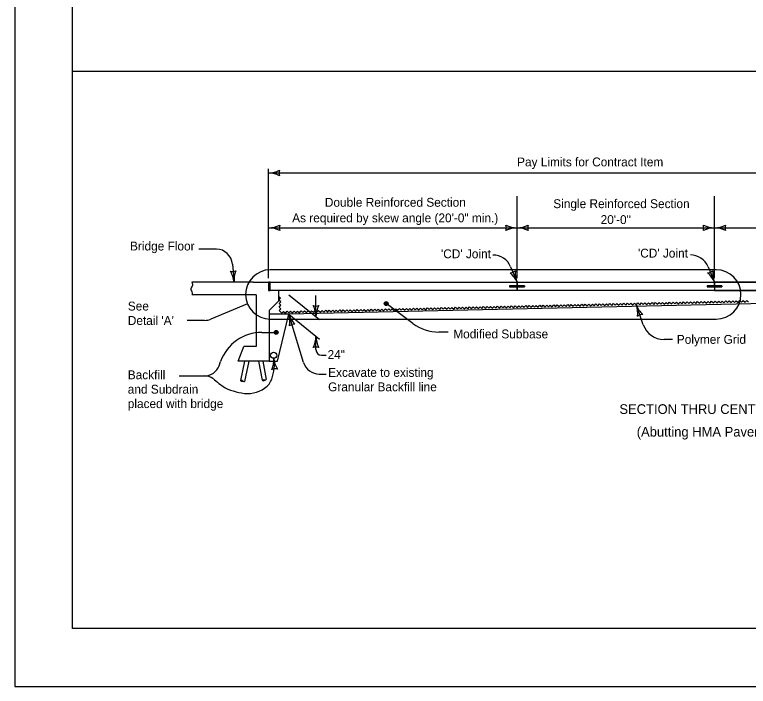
# Model space of a CAD drawing. Extents: x -2135039 to -2124495, y -2139046 to -2132546.
# Drawn here: x -2131439 to -2130115, y -2135130 to -2133919 of the extents above; entities that cross this region are included whole.
import ezdxf

# ---------------------------------------------------------------- set-up
doc = ezdxf.new("R2010")
doc.units = 0
for name, color, linetype in [('BridgeSuperStructureExisting', 7, 'Continuous'), ('dsnAlignmentCurveData', 7, 'Continuous'), ('dsnAlignmentStation', 7, 'Continuous'), ('dsnStdLabel', 7, 'Continuous'), ('dsnStdLineWork', 7, 'Continuous')]:
    doc.layers.add(name, color=color, linetype=linetype)

msp = doc.modelspace()

# ---------------------------------------------------------------- linework, layer by layer
at = {"layer": 'BridgeSuperStructureExisting'}
for p, q in [((-2130980.5, -2134393.9), (-2130980.5, -2134196.9)), ((-2130980.5, -2134204.3), (-2129819.2, -2134204.3)), ((-2130532, -2134393.9), (-2130532, -2134246.4)), ((-2130175.6, -2134393.9), (-2130175.6, -2134246.4)), ((-2130980.5, -2134303.3), (-2130532, -2134303.3)), ((-2130532, -2134303.3), (-2130175.6, -2134303.3)), ((-2130175.6, -2134303.3), (-2129819.2, -2134303.3)), ((-2131074.8, -2134341.7), (-2131106.5, -2134341.7)), ((-2131045.7, -2134368.9), (-2131042.9, -2134401.4)), ((-2130543.6, -2134373.6), (-2130532, -2134401.4)), ((-2130187.2, -2134373.6), (-2130175.6, -2134401.4)), ((-2130172.4, -2134379.1), (-2130977.5, -2134379.1)), ((-2131008.7, -2134401.4), (-2131119.3, -2134401.4)), ((-2131008.7, -2134401.4), (-2130980.5, -2134401.4)), ((-2130980.5, -2134401.4), (-2130980.5, -2134416.2)), ((-2130977.5, -2134401.4), (-2130980.5, -2134401.4)), ((-2130980.5, -2134404.7), (-2130977.5, -2134401.8)), ((-2130980.5, -2134402.6), (-2130979.6, -2134401.8)), ((-2130977.5, -2134401.8), (-2130980.5, -2134401.8)), ((-2130980.5, -2134406.8), (-2130977.5, -2134403.9)), ((-2130977.5, -2134401.4), (-2129819.2, -2134401.4)), ((-2130532, -2134416.2), (-2130532, -2134401.4)), ((-2129819.2, -2134401.4), (-2130175.6, -2134401.4)), ((-2130175.6, -2134401.4), (-2130175.6, -2134407.9)), ((-2130175.6, -2134401.4), (-2130175.6, -2134416.2)), ((-2130980.5, -2134408.9), (-2130977.5, -2134406)), ((-2130980.5, -2134411), (-2130977.5, -2134408.1)), ((-2130980.5, -2134413.1), (-2130977.5, -2134410.2)), ((-2130980.5, -2134415.2), (-2130977.5, -2134412.3)), ((-2130980.5, -2134416.2), (-2130977.5, -2134416.2)), ((-2130979.3, -2134416.2), (-2130977.5, -2134414.4)), ((-2129819.2, -2134416.2), (-2130977.5, -2134416.2)), ((-2130962.7, -2134416.2), (-2130962.7, -2134435.5)), ((-2130545.4, -2134407.9), (-2130518.7, -2134407.9)), ((-2130545.4, -2134409.7), (-2130518.7, -2134409.7)), ((-2130545.4, -2134409.7), (-2130518.7, -2134409.7)), ((-2130518.7, -2134407.9), (-2130518.7, -2134409.7)), ((-2130189, -2134407.9), (-2130162.3, -2134407.9)), ((-2130189, -2134409.7), (-2130162.3, -2134409.7)), ((-2130175.6, -2134407.9), (-2130162.3, -2134407.9)), ((-2130162.3, -2134409.7), (-2130175.6, -2134409.7)), ((-2130175.6, -2134409.7), (-2130175.6, -2134416.2)), ((-2130175.6, -2134416.2), (-2129819.2, -2134416.2)), ((-2130162.3, -2134407.9), (-2130162.3, -2134409.7)), ((-2130162.3, -2134407.9), (-2130162.3, -2134409.7)), ((-2131002.8, -2134424.3), (-2131119.3, -2134424.3)), ((-2131002.8, -2134424.3), (-2131002.8, -2134517.2)), ((-2130943.9, -2134424), (-2130888.6, -2134469)), ((-2130895.1, -2134463.7), (-2130895.1, -2134425.6)), ((-2131018.7, -2134440.7), (-2131084.9, -2134468)), ((-2130962.7, -2134435.5), (-2130979.5, -2134452.3)), ((-2129819.2, -2134433.9), (-2130943.9, -2134459.3)), ((-2130720.3, -2134475.7), (-2130768.3, -2134440.1)), ((-2130304.1, -2134478.3), (-2130316.6, -2134442.4)), ((-2130979.5, -2134452.3), (-2130979.5, -2134543.9)), ((-2131096.2, -2134470.3), (-2131127.8, -2134470.3)), ((-2130943.9, -2134459.3), (-2130979.5, -2134459.3)), ((-2130977.5, -2134468.2), (-2130172.4, -2134468.2)), ((-2130964.6, -2134543.9), (-2130943.9, -2134459.3)), ((-2130943.9, -2134459.3), (-2130888.6, -2134504.3)), ((-2130917.4, -2134546.2), (-2130943.9, -2134459.3)), ((-2130656.2, -2134491.3), (-2130673.1, -2134491.3)), ((-2130895.1, -2134523), (-2130895.1, -2134499)), ((-2130251.3, -2134504.9), (-2130266.7, -2134504.9)), ((-2131035.4, -2134543.9), (-2131025.2, -2134517.2)), ((-2131002.8, -2134517.2), (-2131025.2, -2134517.2)), ((-2130885.1, -2134533), (-2130876.5, -2134533)), ((-2130979.5, -2134543.9), (-2131035.4, -2134543.9)), ((-2131024, -2134543.9), (-2131031.5, -2134578.7)), ((-2131016.4, -2134543.9), (-2131024.2, -2134580.3)), ((-2130998.7, -2134543.9), (-2130992.4, -2134578.3)), ((-2130991.2, -2134543.9), (-2130985.1, -2134576.9)), ((-2130979.5, -2134543.9), (-2130964.6, -2134543.9)), ((-2130889, -2134567.2), (-2130876.5, -2134567.2))]:
    msp.add_line(p, q, dxfattribs=at)
for points in [[(-2130959.7, -2134454.3), (-2130961.5, -2134452.7), (-2130958.4, -2134449.4), (-2130961.6, -2134446.3), (-2130958.5, -2134443.1), (-2130961.7, -2134440), (-2130958.7, -2134436.8), (-2130961.9, -2134433.7), (-2130958.8, -2134430.4), (-2130962, -2134427.3), (-2130961.9, -2134427.2)], [(-2130768, -2134436.9), (-2130769.2, -2134437.5), (-2130771, -2134438), (-2130771.3, -2134439.9), (-2130771.1, -2134441.5), (-2130769.9, -2134443), (-2130768.2, -2134442.8), (-2130766.4, -2134442.6), (-2130765.5, -2134441.1), (-2130765.3, -2134439.6), (-2130766.4, -2134437.6), (-2130767.7, -2134437.4), (-2130769.5, -2134437.9), (-2130771, -2134439), (-2130771, -2134440.8), (-2130769.8, -2134442.2), (-2130768.2, -2134442.3), (-2130766.4, -2134442), (-2130766.1, -2134440.9), (-2130765.7, -2134439.7), (-2130766.6, -2134438.2), (-2130767.9, -2134438.2), (-2130769.4, -2134438.5), (-2130770.5, -2134439.3), (-2130770, -2134440.8), (-2130768.8, -2134441.7), (-2130767.3, -2134441.8), (-2130766.9, -2134441), (-2130766.4, -2134440), (-2130767.2, -2134438.8), (-2130768.3, -2134438.6), (-2130769.3, -2134439.1), (-2130769.4, -2134440.2), (-2130768.8, -2134441), (-2130767.8, -2134441.3), (-2130767.3, -2134440.9), (-2130767, -2134440.3), (-2130767.6, -2134439.3), (-2130768.3, -2134439.2), (-2130769, -2134439.6), (-2130768.9, -2134440.2), (-2130768.4, -2134440.6), (-2130767.6, -2134440.6), (-2130767.7, -2134440.1), (-2130768.3, -2134439.8)], [(-2130597.2, -2134447.2), (-2130595.6, -2134448.7), (-2130592.5, -2134445.5), (-2130589.2, -2134448.6), (-2130586.1, -2134445.3), (-2130582.9, -2134448.4), (-2130579.8, -2134445.2), (-2130576.6, -2134448.3), (-2130573.5, -2134445), (-2130570.2, -2134448.1), (-2130567.1, -2134444.9), (-2130563.9, -2134448), (-2130560.8, -2134444.7), (-2130557.6, -2134447.8), (-2130554.5, -2134444.6), (-2130551.2, -2134447.7), (-2130548.1, -2134444.4), (-2130544.9, -2134447.5), (-2130541.8, -2134444.3), (-2130538.6, -2134447.4), (-2130535.5, -2134444.1), (-2130532.2, -2134447.2), (-2130529.1, -2134444), (-2130525.9, -2134447.1), (-2130522.8, -2134443.8), (-2130521.2, -2134445.4)], [(-2130521.2, -2134445.4), (-2130519.6, -2134446.9), (-2130516.5, -2134443.7), (-2130513.2, -2134446.8), (-2130510.1, -2134443.5), (-2130506.9, -2134446.6), (-2130503.8, -2134443.4), (-2130500.6, -2134446.5), (-2130497.5, -2134443.2), (-2130494.2, -2134446.3), (-2130491.1, -2134443.1), (-2130487.9, -2134446.2), (-2130484.8, -2134442.9), (-2130481.6, -2134446), (-2130478.5, -2134442.8), (-2130475.2, -2134445.9), (-2130472.1, -2134442.6), (-2130468.9, -2134445.7), (-2130465.8, -2134442.5), (-2130462.6, -2134445.6), (-2130459.5, -2134442.3), (-2130456.2, -2134445.4), (-2130453.1, -2134442.2), (-2130449.9, -2134445.3), (-2130446.8, -2134442), (-2130445.2, -2134443.6)], [(-2130445.2, -2134443.6), (-2130443.6, -2134445.1), (-2130440.5, -2134441.9), (-2130437.2, -2134445), (-2130434.1, -2134441.7), (-2130430.9, -2134444.8), (-2130427.8, -2134441.6), (-2130424.6, -2134444.7), (-2130421.5, -2134441.4), (-2130418.2, -2134444.5), (-2130415.1, -2134441.3), (-2130411.9, -2134444.4), (-2130408.8, -2134441.1), (-2130405.5, -2134444.2), (-2130402.5, -2134441), (-2130399.2, -2134444.1), (-2130396.1, -2134440.8), (-2130392.9, -2134443.9), (-2130389.8, -2134440.7), (-2130386.5, -2134443.8), (-2130383.5, -2134440.5), (-2130380.2, -2134443.6), (-2130377.1, -2134440.4), (-2130373.9, -2134443.5), (-2130370.8, -2134440.2), (-2130369.2, -2134441.8)], [(-2130369.2, -2134441.8), (-2130367.5, -2134443.4), (-2130364.4, -2134440.1), (-2130361.2, -2134443.2), (-2130358.1, -2134440), (-2130354.9, -2134443.1), (-2130351.8, -2134439.8), (-2130348.5, -2134442.9), (-2130345.4, -2134439.7), (-2130342.2, -2134442.8), (-2130339.1, -2134439.5), (-2130335.9, -2134442.6), (-2130332.8, -2134439.4), (-2130329.5, -2134442.5), (-2130326.4, -2134439.2), (-2130323.2, -2134442.3), (-2130320.1, -2134439.1), (-2130316.9, -2134442.2), (-2130313.8, -2134438.9), (-2130310.5, -2134442), (-2130307.4, -2134438.8), (-2130304.2, -2134441.9), (-2130301.1, -2134438.6), (-2130297.9, -2134441.7), (-2130294.8, -2134438.5), (-2130293.2, -2134440)], [(-2130293.2, -2134440), (-2130291.5, -2134441.6), (-2130288.4, -2134438.3), (-2130285.2, -2134441.4), (-2130282.1, -2134438.2), (-2130278.9, -2134441.3), (-2130275.8, -2134438), (-2130272.5, -2134441.1), (-2130269.4, -2134437.9), (-2130266.2, -2134441), (-2130263.1, -2134437.8), (-2130259.9, -2134440.8), (-2130256.8, -2134437.6), (-2130253.5, -2134440.7), (-2130250.4, -2134437.5), (-2130247.2, -2134440.5), (-2130244.1, -2134437.3), (-2130240.9, -2134440.4), (-2130237.8, -2134437.2), (-2130234.5, -2134440.3), (-2130231.4, -2134437), (-2130228.2, -2134440.1), (-2130225.1, -2134436.9), (-2130221.9, -2134440), (-2130218.8, -2134436.7), (-2130217.1, -2134438.3)], [(-2130217.1, -2134438.3), (-2130215.5, -2134439.8), (-2130212.4, -2134436.6), (-2130209.2, -2134439.7), (-2130206.1, -2134436.4), (-2130202.9, -2134439.5), (-2130199.8, -2134436.3), (-2130196.5, -2134439.4), (-2130193.4, -2134436.1), (-2130190.2, -2134439.2), (-2130187.1, -2134436), (-2130183.8, -2134439.1), (-2130180.8, -2134435.8), (-2130177.5, -2134438.9), (-2130174.4, -2134435.7), (-2130171.2, -2134438.8), (-2130168.1, -2134435.5), (-2130164.8, -2134438.6), (-2130161.8, -2134435.4), (-2130158.5, -2134438.5), (-2130155.4, -2134435.2), (-2130152.2, -2134438.3), (-2130149.1, -2134435.1), (-2130145.8, -2134438.2), (-2130142.8, -2134435), (-2130141.1, -2134436.5)], [(-2130141.1, -2134436.5), (-2130139.5, -2134438), (-2130136.4, -2134434.8), (-2130133.2, -2134437.9), (-2130130.1, -2134434.6), (-2130126.8, -2134437.7), (-2130123.7, -2134434.5), (-2130120.5, -2134437.6), (-2130117.4, -2134434.3), (-2130114.2, -2134437.4)], [(-2130959.9, -2134454.2), (-2130959.9, -2134454.1), (-2130956.6, -2134457.2), (-2130953.5, -2134454), (-2130950.3, -2134457.1), (-2130947.2, -2134453.8), (-2130944, -2134456.9), (-2130940.9, -2134453.7), (-2130937.6, -2134456.8), (-2130934.5, -2134453.5), (-2130931.3, -2134456.6), (-2130928.2, -2134453.4), (-2130925, -2134456.5), (-2130921.9, -2134453.2), (-2130918.6, -2134456.3), (-2130915.5, -2134453.1), (-2130912.3, -2134456.2), (-2130909.2, -2134452.9), (-2130906, -2134456), (-2130902.9, -2134452.8), (-2130901.2, -2134454.3)], [(-2130901.2, -2134454.3), (-2130899.6, -2134455.8), (-2130896.5, -2134452.6), (-2130893.3, -2134455.7), (-2130890.2, -2134452.4), (-2130886.9, -2134455.5), (-2130883.9, -2134452.3), (-2130880.6, -2134455.4), (-2130877.5, -2134452.1), (-2130874.3, -2134455.2), (-2130871.2, -2134452), (-2130867.9, -2134455.1), (-2130864.9, -2134451.8), (-2130861.6, -2134454.9), (-2130858.5, -2134451.7), (-2130855.3, -2134454.8), (-2130852.2, -2134451.5), (-2130848.9, -2134454.6), (-2130845.8, -2134451.4), (-2130842.6, -2134454.5), (-2130839.5, -2134451.3), (-2130836.3, -2134454.3), (-2130833.2, -2134451.1), (-2130829.9, -2134454.2), (-2130826.8, -2134451), (-2130825.2, -2134452.5)], [(-2130825.2, -2134452.5), (-2130823.6, -2134454), (-2130820.5, -2134450.8), (-2130817.3, -2134453.9), (-2130814.2, -2134450.7), (-2130810.9, -2134453.7), (-2130807.8, -2134450.5), (-2130804.6, -2134453.6), (-2130801.5, -2134450.4), (-2130798.3, -2134453.4), (-2130795.2, -2134450.2), (-2130791.9, -2134453.3), (-2130788.8, -2134450.1), (-2130785.6, -2134453.1), (-2130782.5, -2134449.9), (-2130779.3, -2134453), (-2130776.2, -2134449.8), (-2130772.9, -2134452.9), (-2130769.8, -2134449.6), (-2130766.6, -2134452.7), (-2130763.5, -2134449.5), (-2130760.3, -2134452.6), (-2130757.2, -2134449.3), (-2130753.9, -2134452.4), (-2130750.8, -2134449.2), (-2130749.2, -2134450.7)], [(-2130749.2, -2134450.7), (-2130747.6, -2134452.2), (-2130744.5, -2134449), (-2130741.3, -2134452.1), (-2130738.2, -2134448.9), (-2130734.9, -2134452), (-2130731.8, -2134448.7), (-2130728.6, -2134451.8), (-2130725.5, -2134448.6), (-2130722.3, -2134451.7), (-2130719.2, -2134448.4), (-2130715.9, -2134451.5), (-2130712.8, -2134448.3), (-2130709.6, -2134451.4), (-2130706.5, -2134448.1), (-2130703.3, -2134451.2), (-2130700.2, -2134448), (-2130696.9, -2134451.1), (-2130693.8, -2134447.8), (-2130690.6, -2134450.9), (-2130687.5, -2134447.7), (-2130684.3, -2134450.8), (-2130681.2, -2134447.5), (-2130677.9, -2134450.6), (-2130674.8, -2134447.4), (-2130673.2, -2134448.9)], [(-2130673.2, -2134448.9), (-2130671.6, -2134450.5), (-2130668.5, -2134447.2), (-2130665.2, -2134450.3), (-2130662.2, -2134447.1), (-2130658.9, -2134450.2), (-2130655.8, -2134446.9), (-2130652.6, -2134450), (-2130649.5, -2134446.8), (-2130646.3, -2134449.9), (-2130643.2, -2134446.6), (-2130639.9, -2134449.7), (-2130636.8, -2134446.5), (-2130633.6, -2134449.6), (-2130630.5, -2134446.3), (-2130627.3, -2134449.4), (-2130624.2, -2134446.2), (-2130620.9, -2134449.3), (-2130617.8, -2134446), (-2130614.6, -2134449.1), (-2130611.5, -2134445.9), (-2130608.2, -2134449), (-2130605.1, -2134445.7), (-2130601.9, -2134448.8), (-2130598.8, -2134445.6), (-2130597.2, -2134447.1)], [(-2130967.2, -2134495.2), (-2130966, -2134494.6), (-2130964.2, -2134494.1), (-2130963.9, -2134492.2), (-2130964.1, -2134490.6), (-2130965.3, -2134489.1), (-2130967, -2134489.3), (-2130968.8, -2134489.5), (-2130969.7, -2134491), (-2130969.9, -2134492.5), (-2130968.8, -2134494.5), (-2130967.5, -2134494.7), (-2130965.6, -2134494.2), (-2130964.1, -2134493.1), (-2130964.2, -2134491.3), (-2130965.4, -2134489.9), (-2130967, -2134489.8), (-2130968.8, -2134490.1), (-2130969.1, -2134491.2), (-2130969.5, -2134492.4), (-2130968.6, -2134493.9), (-2130967.3, -2134493.9), (-2130965.8, -2134493.6), (-2130964.7, -2134492.8), (-2130965.2, -2134491.3), (-2130966.4, -2134490.4), (-2130967.9, -2134490.3), (-2130968.3, -2134491.1), (-2130968.8, -2134492.1), (-2130968, -2134493.3), (-2130966.9, -2134493.6), (-2130965.9, -2134493), (-2130965.8, -2134491.9), (-2130966.3, -2134491.1), (-2130967.4, -2134490.8), (-2130967.9, -2134491.2), (-2130968.2, -2134491.9), (-2130967.6, -2134492.8), (-2130966.9, -2134492.9), (-2130966.2, -2134492.5), (-2130966.3, -2134491.9), (-2130966.8, -2134491.5), (-2130967.6, -2134491.5), (-2130967.5, -2134492), (-2130966.9, -2134492.3)]]:
    msp.add_lwpolyline(points, dxfattribs=at)
for centre, radius in [((-2130768.3, -2134440.1), 3.46), ((-2130966.9, -2134492), 3.46), ((-2130971.5, -2134533.2), 5.57)]:
    msp.add_circle(centre, radius, dxfattribs=at)
for centre, radius, start, end in [((-2130981.1, -2134161.6), 42.7, 270, 298.0725), ((-2130981.1, -2134247.1), 42.7, 61.9275, 90), ((-2130945.2, -2134204.4), 16.5, 162.2666, 197.7334), ((-2130980.5, -2134260.6), 42.7, 270, 298.0725), ((-2130944.7, -2134303.3), 16.5, 162.2666, 197.7334), ((-2130567.9, -2134303.3), 16.5, 342.2666, 17.7333), ((-2130532, -2134260.6), 42.7, 241.9275, 270), ((-2130532, -2134260.6), 42.7, 270, 298.0725), ((-2130496.2, -2134303.3), 16.5, 162.2666, 197.7334), ((-2130211.5, -2134303.3), 16.5, 342.2666, 17.7333), ((-2130175.6, -2134260.6), 42.7, 241.9275, 270), ((-2130175.6, -2134260.6), 42.7, 270, 298.0725), ((-2130139.8, -2134303.3), 16.5, 162.2666, 197.7334), ((-2130980.5, -2134346.1), 42.7, 61.9275, 90), ((-2130532, -2134346.1), 42.7, 90, 118.0725), ((-2130532, -2134346.1), 42.7, 61.9275, 90), ((-2130175.6, -2134346.1), 42.7, 90, 118.0725), ((-2130175.6, -2134346.1), 42.7, 61.9275, 90), ((-2131075.3, -2134371.4), 29.7, 4.9696, 89.1065), ((-2130575.6, -2134387), 34.6, 22.5907, 90), ((-2130219.2, -2134386.9), 34.6, 22.5907, 90), ((-2131046, -2134365.7), 16.5, 257.2356, 292.7023), ((-2131085.4, -2134405.1), 42.7, 4.969, 33.0415), ((-2131000.3, -2134397.7), 42.7, 156.8965, 184.969), ((-2130977.5, -2134423.6), 44.5, 90, 269.9998), ((-2130545.8, -2134368.3), 16.5, 274.8595, 310.3262), ((-2130571.5, -2134417.8), 42.7, 22.5928, 50.6653), ((-2130492.6, -2134384.9), 42.7, 174.5203, 202.5928), ((-2130189.4, -2134368.3), 16.5, 274.8572, 310.3239), ((-2130215.1, -2134417.8), 42.7, 22.5905, 50.663), ((-2130136.2, -2134384.9), 42.7, 174.5181, 202.5905), ((-2130172.4, -2134423.6), 44.5, 270.0002, 90), ((-2130895.1, -2134427.9), 16.5, 252.2666, 287.7333), ((-2130937.8, -2134463.7), 42.7, 360, 28.0725), ((-2130852.3, -2134463.7), 42.7, 151.9275, 180), ((-2130276.2, -2134428.3), 42.7, 199.1779, 227.2504), ((-2130357, -2134456.4), 42.7, 351.1054, 19.1779), ((-2131096.2, -2134440.6), 29.7, 270, 292.4496), ((-2130903, -2134446.8), 42.7, 196.9537, 225.0262), ((-2130984.8, -2134471.8), 42.7, 348.8812, 16.9537), ((-2130903, -2134446.8), 42.7, 196.9537, 225.0262), ((-2130984.8, -2134471.8), 42.7, 348.8812, 16.9537), ((-2130304.8, -2134476.2), 16.5, 91.4446, 126.9113), ((-2130933.4, -2134493.6), 16.5, 89.2203, 124.687), ((-2130933.4, -2134493.6), 16.5, 89.2203, 124.687), ((-2130673.1, -2134412.1), 79.2, 233.4243, 270), ((-2130266.7, -2134465.3), 39.6, 199.1769, 270), ((-2130992.7, -2134571.2), 79.2, 90, 160.3012), ((-2130937.8, -2134499), 42.7, 331.9275, 360), ((-2130852.3, -2134499), 42.7, 180, 208.0725), ((-2130895.1, -2134534.9), 16.5, 72.2666, 107.7334), ((-2130885.1, -2134523), 10, 180, 270), ((-2131013.6, -2134542.7), 42.5, 337.1139, 5.1864), ((-2130929, -2134535), 42.5, 185.1864, 213.2589), ((-2130889, -2134537.5), 29.7, 196.9535, 270), ((-2131096.1, -2134542.7), 27.7, 270, 340.3019), ((-2130968.1, -2134574.3), 16.4, 77.453, 112.9197), ((-2131096.1, -2134598.2), 27.7, 56.8248, 90)]:
    msp.add_arc(centre, radius, start, end, dxfattribs=at)
for points in [[(-2131119.3, -2134401.4), (-2131118.1, -2134407.3), (-2131121.1, -2134413.3), (-2131118.4, -2134421), (-2131118.8, -2134424.3)], [(-2130992.4, -2134578.3), (-2130989.6, -2134577.1), (-2130986.8, -2134578.3), (-2130985.1, -2134576.9)], [(-2131031.5, -2134578.7), (-2131028.4, -2134578.4), (-2131026.6, -2134580.1), (-2131024.2, -2134580.3)], [(-2131031.5, -2134578.7), (-2131029.4, -2134580.2), (-2131027, -2134580)], [(-2130992.4, -2134578.3), (-2130989.7, -2134579.2), (-2130987.6, -2134578.3)]]:
    msp.add_spline(points, degree=3, dxfattribs=at)
at = {"layer": 'dsnAlignmentCurveData'}
msp.add_line((-2131334.4, -2134021), (-2128199.4, -2134021), dxfattribs=at)
at = {"layer": 'dsnAlignmentStation'}
msp.add_lwpolyline([(-2131334.4, -2133016), (-2128199.4, -2133016), (-2128199.4, -2135026), (-2131334.4, -2135026)], close=True, dxfattribs=at)
at = {"layer": 'dsnStdLabel'}
for p, q in [((-2130977.5, -2134416.2), (-2130977.5, -2134401.4)), ((-2130977.5, -2134401.4), (-2130532, -2134401.4)), ((-2130977.5, -2134416.2), (-2130977.5, -2134401.4)), ((-2130532, -2134401.4), (-2130532, -2134407.9)), ((-2130532, -2134407.9), (-2130532, -2134401.4)), ((-2130532, -2134407.9), (-2130532, -2134401.4)), ((-2130532, -2134401.4), (-2130175.6, -2134401.4)), ((-2130175.6, -2134407.9), (-2130175.6, -2134401.4)), ((-2130175.6, -2134401.4), (-2130175.6, -2134407.9)), ((-2130962.2, -2134416.2), (-2130977.5, -2134416.2)), ((-2130940.4, -2134416.2), (-2130962.2, -2134416.2)), ((-2130532, -2134416.2), (-2130940.4, -2134416.2)), ((-2130545.4, -2134407.9), (-2130545.4, -2134409.7)), ((-2130532, -2134407.9), (-2130545.4, -2134407.9)), ((-2130545.4, -2134407.9), (-2130545.4, -2134409.7)), ((-2130545.4, -2134407.9), (-2130545.4, -2134409.7)), ((-2130518.7, -2134407.9), (-2130545.4, -2134407.9)), ((-2130545.4, -2134407.9), (-2130532, -2134407.9)), ((-2130545.4, -2134409.7), (-2130532.1, -2134409.7)), ((-2130532.1, -2134409.7), (-2130532, -2134416.2)), ((-2130532, -2134416.2), (-2130532.1, -2134409.7)), ((-2130518.7, -2134407.9), (-2130532, -2134407.9)), ((-2130518.7, -2134407.9), (-2130532, -2134407.9)), ((-2130532, -2134409.8), (-2130518.7, -2134409.7)), ((-2130532, -2134416.2), (-2130532, -2134409.8)), ((-2130175.6, -2134416.2), (-2130532, -2134416.2)), ((-2130518.7, -2134409.7), (-2130518.7, -2134407.9)), ((-2130518.7, -2134409.7), (-2130518.7, -2134407.9)), ((-2130189, -2134407.9), (-2130189, -2134409.7)), ((-2130175.6, -2134407.9), (-2130189, -2134407.9)), ((-2130189, -2134407.9), (-2130189, -2134409.7)), ((-2130189, -2134409.7), (-2130175.6, -2134409.7)), ((-2130162.3, -2134407.9), (-2130175.6, -2134407.9)), ((-2130175.6, -2134409.7), (-2130175.6, -2134416.2)), ((-2130992.7, -2134492), (-2130966.9, -2134492)), ((-2131070, -2134552.1), (-2131067.3, -2134544.5)), ((-2131141.8, -2134570.4), (-2131096.1, -2134570.4))]:
    msp.add_line(p, q, dxfattribs=at)
for centre, radius, start, end in [((-2131041.3, -2134550.1), 71.3, 330.5092, 2.0511), ((-2130969.6, -2134455), 163.6, 227.1442, 236.9942), ((-2131019.3, -2134547.5), 55, 270.3325, 316.7198), ((-2131009.8, -2134484.3), 118.5, 245.5915, 265.546)]:
    msp.add_arc(centre, radius, start, end, dxfattribs=at)
at = {"layer": 'dsnStdLineWork'}
msp.add_lwpolyline([(-2131438.9, -2135130.5), (-2128094.9, -2135130.5), (-2128094.9, -2132546.5), (-2131438.9, -2132546.5)], close=True, dxfattribs=at)

# ---------------------------------------------------------------- texts
at = {"layer": 'BridgeSuperStructureExisting'}
msp.add_text('SECTION THRU CENTERLINE', height=17.5, dxfattribs=at).set_placement((-2130347.3, -2134639.1))
at = {"layer": 'dsnStdLabel'}
for s, height, p in [('Pay Limits for Contract Item', 16, (-2130532, -2134192.5)), ('Double Reinforced Section', 16, (-2130879, -2134265.3)), ('Single Reinforced Section', 16, (-2130466.7, -2134267.8)), ('As required by skew angle (20\'-0" min.)', 16, (-2130938, -2134293.4)), ('20\'-0"', 16, (-2130381.2, -2134296.5)), ('Bridge Floor', 16, (-2131230.7, -2134344.2)), ("'CD' Joint", 16, (-2130669.4, -2134358.2)), ("'CD' Joint", 16, (-2130313.8, -2134357)), ('See', 16, (-2131234.7, -2134452.5)), ("Detail 'A'", 16, (-2131234.7, -2134478.5)), ('Modified Subbase', 16, (-2130647.2, -2134502.8)), ('Polymer Grid', 16, (-2130243.6, -2134512.6)), ('24"', 16, (-2130874.1, -2134540)), ('Backfill', 16, (-2131234.8, -2134576.5)), ('Excavate to existing', 16, (-2130873.1, -2134572.2)), ('and Subdrain', 16, (-2131234.8, -2134602.5)), ('Granular Backfill line', 16, (-2130873.1, -2134598.2)), ('placed with bridge', 16, (-2131234.8, -2134628.5)), ('(Abutting HMA Pavement)', 17.5, (-2130316, -2134680))]:
    msp.add_text(s, height=height, dxfattribs=at).set_placement(p)

doc.saveas('drawing.dxf')
